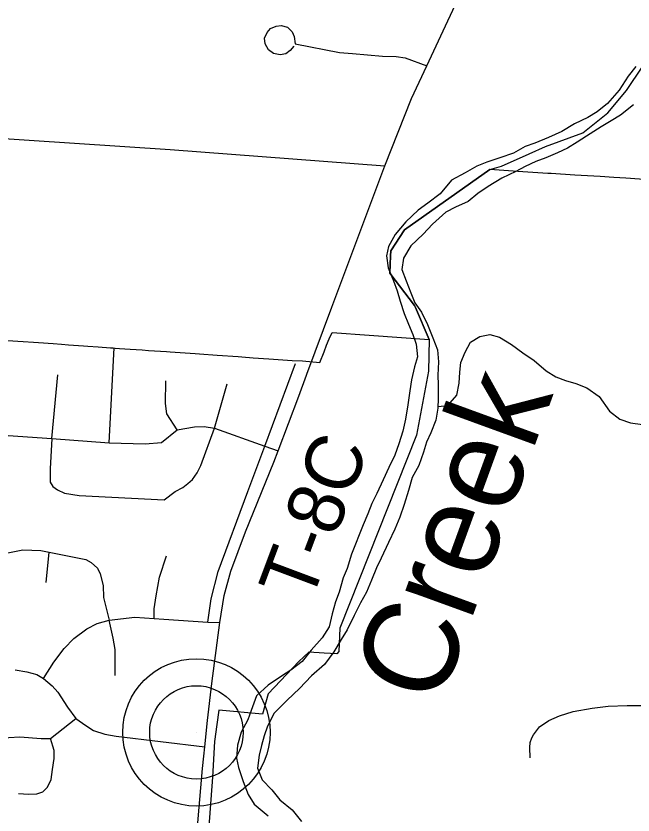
# Model space of a CAD drawing. Extents: x 0 to 34, y 0 to 22.
# Drawn here: x 6.527 to 7.149, y 18.131 to 18.938 of the extents above; entities that cross this region are included whole.
import ezdxf

# ---------------------------------------------------------------- set-up
doc = ezdxf.new("R2010")
doc.units = 0
for name, color, linetype in [('GM_X_City_Street', 7, 'Continuous'), ('GM_X_Corporation', 7, 'Continuous'), ('GM_X_County_Road', 7, 'Continuous'), ('GM_X_Major_River', 7, 'Continuous'), ('GM_X_Major_River_Text', 7, 'Continuous'), ('GM_X_Minor_River', 7, 'Continuous'), ('GM_X_Township_Road', 7, 'Continuous'), ('GM_X_Township_Road_Text', 7, 'Continuous'), ('GM_X_Unincorporated', 7, 'Continuous'), ('GM_X_Unincorporated_Location', 7, 'Continuous')]:
    doc.layers.add(name, color=color, linetype=linetype)

msp = doc.modelspace()

# ---------------------------------------------------------------- linework, layer by layer
at = {"layer": 'GM_X_City_Street'}
for points in [[(6.80693, 18.90727), (6.80336, 18.90299), (6.79908, 18.89966), (6.79338, 18.89871), (6.78649, 18.8999), (6.7815, 18.9037), (6.77817, 18.90964), (6.77746, 18.91558), (6.78008, 18.92129), (6.78364, 18.92509), (6.78934, 18.92746), (6.79433, 18.92818), (6.80075, 18.92651), (6.8055, 18.922), (6.8074, 18.91701), (6.80859, 18.90964), (6.85326, 18.90085), (6.86633, 18.8999), (6.89651, 18.89729), (6.91029, 18.89681), (6.91932, 18.89562), (6.94123, 18.88763)], [(7.04579, 18.18856), (7.04533, 18.19922), (7.04579, 18.20399), (7.04738, 18.20899), (7.04919, 18.21193), (7.05509, 18.21988), (7.06462, 18.22646), (7.07529, 18.231), (7.08913, 18.23554), (7.10815, 18.23891), (7.12441, 18.24084), (7.14343, 18.24139), (7.1619, 18.24139)]]:
    msp.add_lwpolyline(points, dxfattribs=at)
at = {"layer": 'GM_X_Corporation'}
for points in [[(6.51797, 18.61029), (6.53378, 18.60916), (6.54424, 18.60841), (6.54931, 18.60805), (6.56427, 18.60698), (6.57265, 18.60638), (6.57948, 18.6059), (6.59463, 18.60481), (6.59907, 18.6045), (6.60968, 18.60374), (6.62186, 18.60287), (6.62479, 18.60264), (6.62664, 18.60246), (6.63121, 18.60215), (6.64189, 18.60141), (6.65396, 18.60057), (6.66047, 18.60012), (6.67842, 18.59887), (6.68237, 18.59859), (6.70759, 18.59684), (6.71171, 18.59655), (6.72985, 18.59529), (6.75097, 18.59383), (6.75476, 18.59356), (6.76608, 18.59278), (6.78181, 18.59168), (6.80547, 18.59004), (6.81587, 18.58964), (6.83343, 18.58777), (6.8376, 18.59878), (6.8399, 18.60533), (6.84262, 18.61172), (6.84583, 18.61812), (6.88317, 18.61553), (6.94378, 18.61101), (6.92994, 18.6434), (6.92905, 18.64548), (6.90387, 18.67806), (6.90475, 18.69567), (6.905, 18.70079), (6.91892, 18.72181), (7.00507, 18.78268), (7.0166, 18.78615), (7.04449, 18.79861), (7.0612, 18.80608), (7.09889, 18.81996), (7.12418, 18.84003), (7.14302, 18.86275), (7.1594, 18.88705)], [(7.16495, 18.77243), (7.14235, 18.77407), (7.13021, 18.77481), (7.11617, 18.77567), (7.09091, 18.77721), (7.06694, 18.77867), (7.06361, 18.77888), (7.03321, 18.78074), (7.00507, 18.78268), (6.91892, 18.72181), (6.905, 18.70079), (6.90475, 18.69567), (6.90387, 18.67806), (6.92905, 18.64548), (6.92994, 18.6434), (6.94378, 18.61101), (6.9431, 18.57906), (6.93091, 18.51445), (6.85367, 18.31952), (6.85266, 18.29603), (6.85053, 18.29377), (6.8376, 18.29449), (6.82207, 18.29535), (6.81204, 18.28579), (6.78113, 18.25327), (6.77561, 18.23283), (6.73135, 18.23679), (6.72943, 18.22219), (6.72712, 18.20511), (6.72493, 18.16895), (6.7208, 18.11481)]]:
    msp.add_lwpolyline(points, dxfattribs=at)
at = {"layer": 'GM_X_County_Road'}
for points in [[(6.81991, 18.57517), (6.82026, 18.57613), (6.84538, 18.64365), (6.89881, 18.78652), (6.92594, 18.85442), (6.94123, 18.88763), (6.98628, 18.98446), (6.99992, 19.01307), (7.01571, 19.04496), (7.0282, 19.06781), (7.03543, 19.08163), (7.03988, 19.09116), (7.04415, 19.103), (7.04859, 19.11845), (7.05335, 19.14344), (7.08739, 19.34698), (7.09396, 19.37969), (7.09988, 19.41388), (7.10909, 19.47093), (7.10953, 19.47384)], [(6.30332, 18.82829), (6.34149, 18.82565), (6.68224, 18.80302), (6.89881, 18.78652)], [(6.71622, 18.19016), (6.71715, 18.1996), (6.71995, 18.22623), (6.72445, 18.26359), (6.73244, 18.3252), (6.73688, 18.35249), (6.74362, 18.37731), (6.75825, 18.41694), (6.78702, 18.4873), (6.7913, 18.49881), (6.81225, 18.55396), (6.81991, 18.57517)], [(6.68696, 17.79692), (6.69374, 17.89363), (6.69474, 17.90859), (6.69527, 17.91537), (6.69562, 17.92042), (6.69631, 17.93021), (6.69763, 17.94915), (6.69862, 17.96322), (6.69895, 17.96788), (6.70303, 18.026), (6.7034, 18.03105), (6.71041, 18.1271), (6.71501, 18.17789), (6.71622, 18.19016)]]:
    msp.add_lwpolyline(points, dxfattribs=at)
at = {"layer": 'GM_X_Major_River'}
for points in [[(7.15229, 18.88687), (7.14466, 18.87703), (7.13549, 18.86302), (7.12366, 18.84941), (7.11338, 18.84111), (7.10387, 18.83545), (7.09056, 18.82906), (7.07763, 18.82115), (7.06432, 18.81513), (7.05026, 18.80951), (7.04076, 18.80613), (7.02897, 18.79935), (7.01491, 18.79448), (7.00199, 18.79036), (6.99173, 18.78623), (6.97994, 18.77945), (6.96625, 18.77192), (6.9548, 18.75831), (6.94224, 18.74888), (6.93272, 18.74171), (6.92015, 18.73), (6.90946, 18.71714), (6.90258, 18.70502), (6.90063, 18.69554), (6.90247, 18.68338), (6.90772, 18.67045), (6.91146, 18.66018)], [(7.14983, 18.84815), (7.13688, 18.83758), (7.12737, 18.83193), (7.11748, 18.8259), (7.10264, 18.81648), (7.09313, 18.81045), (7.08323, 18.80442), (7.07335, 18.79953), (7.06157, 18.79465), (7.05131, 18.7909), (7.04066, 18.78601), (7.03115, 18.78074), (7.01709, 18.77397), (7.00339, 18.76568), (6.99273, 18.75851), (6.98321, 18.75059)], [(6.98321, 18.75059), (6.97029, 18.74495), (6.9604, 18.73968), (6.94707, 18.72759), (6.93753, 18.71739), (6.92534, 18.70567), (6.91769, 18.69318), (6.91612, 18.6818), (6.92061, 18.67039), (6.92511, 18.65822), (6.92923, 18.64833), (6.93601, 18.63881), (6.94202, 18.62625), (6.94726, 18.61294), (6.95214, 18.60077), (6.95321, 18.58862), (6.95239, 18.57495), (6.95272, 18.56546), (6.95265, 18.55141), (6.95261, 18.54192), (6.95027, 18.52978), (6.94528, 18.5169), (6.94106, 18.50742), (6.93797, 18.49719), (6.93336, 18.48392), (6.92647, 18.4718), (6.92299, 18.45853), (6.91837, 18.44451), (6.91414, 18.43162), (6.90915, 18.41949), (6.90263, 18.40623), (6.89535, 18.39032), (6.89037, 18.38047), (6.88537, 18.36797), (6.88038, 18.35584), (6.87426, 18.34524), (6.86813, 18.33236), (6.86085, 18.31797), (6.85474, 18.30812), (6.84747, 18.29563), (6.83792, 18.28276), (6.82497, 18.27143), (6.81277, 18.25858), (6.80019, 18.24687), (6.78723, 18.23364), (6.78034, 18.22076), (6.77726, 18.21091), (6.77456, 18.20105), (6.77223, 18.19119), (6.77027, 18.17829), (6.77515, 18.1665), (6.78496, 18.1562), (6.79287, 18.14629), (6.80534, 18.13598), (6.81477, 18.12417)], [(6.91146, 18.66018), (6.91445, 18.64992), (6.91856, 18.63737), (6.92268, 18.62672), (6.92718, 18.61607), (6.93055, 18.60656), (6.932, 18.59365), (6.92891, 18.58341), (6.92581, 18.57052), (6.92424, 18.55913), (6.92228, 18.5451), (6.91993, 18.53068), (6.91722, 18.51854), (6.91298, 18.50566), (6.90913, 18.49428), (6.903, 18.48178), (6.89725, 18.46928), (6.89074, 18.45564), (6.88576, 18.44542), (6.88191, 18.43518), (6.87692, 18.42382), (6.8654, 18.39426), (6.86078, 18.37985), (6.85694, 18.37037), (6.85269, 18.35597), (6.84923, 18.34611), (6.84576, 18.33398), (6.84266, 18.32109), (6.83578, 18.30973), (6.82472, 18.29725), (6.81556, 18.2859), (6.80414, 18.27722), (6.79463, 18.27119), (6.7813, 18.26214), (6.76949, 18.25119), (6.76411, 18.2364), (6.76065, 18.22693), (6.75376, 18.21443), (6.75028, 18.20154), (6.74908, 18.18826), (6.75131, 18.17875), (6.75579, 18.16469), (6.76104, 18.15175), (6.76706, 18.14186), (6.78104, 18.13002)]]:
    msp.add_lwpolyline(points, dxfattribs=at)
at = {"layer": 'GM_X_Minor_River'}
msp.add_lwpolyline([(6.95262, 18.54341), (6.96245, 18.5445), (6.97164, 18.55504), (6.97402, 18.56717), (6.9745, 18.57818), (6.97573, 18.58804), (6.97999, 18.59825), (6.98539, 18.60846), (6.99491, 18.61406), (7.00479, 18.61625), (7.01462, 18.6135), (7.02668, 18.60617), (7.03835, 18.59771), (7.04965, 18.59001), (7.06169, 18.57964), (7.07149, 18.57348), (7.0813, 18.56959), (7.09189, 18.56683), (7.10284, 18.56217), (7.11527, 18.5537), (7.12575, 18.5388), (7.13629, 18.53072), (7.14687, 18.52683), (7.15898, 18.52519)], dxfattribs=at)
at = {"layer": 'GM_X_Township_Road'}
for p, q in [((6.62066, 18.50691), (6.62588, 18.60267)), ((6.56265, 18.5113), (6.56884, 18.57541)), ((6.72685, 18.5215), (6.73984, 18.56622)), ((6.55695, 18.36579), (6.56007, 18.39642))]:
    msp.add_line(p, q, dxfattribs=at)
for points in [[(6.72028, 18.32553), (6.72364, 18.34914), (6.73063, 18.37682), (6.76071, 18.45755), (6.77798, 18.50325), (6.80889, 18.58693)], [(6.6892, 18.52002), (6.67887, 18.53609), (6.67751, 18.54637), (6.67785, 18.56956)], [(6.37595, 18.3513), (6.37661, 18.37871), (6.37787, 18.41068), (6.3803, 18.42052), (6.38462, 18.42996), (6.42368, 18.46649), (6.46574, 18.50202), (6.47088, 18.50582), (6.4858, 18.51167), (6.49953, 18.51488), (6.50865, 18.51474), (6.56265, 18.5113), (6.62066, 18.50691), (6.65713, 18.50563), (6.67351, 18.50727), (6.6892, 18.52002), (6.70696, 18.52298), (6.71649, 18.52314), (6.72685, 18.5215), (6.77798, 18.50325), (6.7913, 18.49881)], [(6.56265, 18.5113), (6.56098, 18.48049), (6.56116, 18.46718), (6.56375, 18.46257), (6.56865, 18.45945), (6.57544, 18.45593), (6.59022, 18.45343), (6.67607, 18.44906), (6.68739, 18.45771), (6.69495, 18.46182), (6.70005, 18.46561), (6.70465, 18.46971), (6.70942, 18.47645), (6.7132, 18.48385), (6.72685, 18.5215)], [(6.44891, 18.28813), (6.4527, 18.30519), (6.46154, 18.32319), (6.4726, 18.34466), (6.48776, 18.37088), (6.50179, 18.38521), (6.5068, 18.38969), (6.5114, 18.39266), (6.51829, 18.3956), (6.53354, 18.39878), (6.55173, 18.39807), (6.56007, 18.39642), (6.59726, 18.38907), (6.60253, 18.38594), (6.6089, 18.38014), (6.61148, 18.37439), (6.61472, 18.36267), (6.61504, 18.35066), (6.62056, 18.32777)], [(6.66619, 18.32948), (6.66607, 18.33896), (6.66817, 18.35224), (6.67149, 18.3712), (6.67865, 18.39276)], [(6.55439, 18.26886), (6.56482, 18.28513), (6.57509, 18.29903), (6.58503, 18.30929), (6.59798, 18.31876), (6.60857, 18.32429), (6.62056, 18.32777), (6.64646, 18.33079), (6.66619, 18.32948), (6.67589, 18.32866), (6.72028, 18.32553), (6.73244, 18.3252)], [(6.62657, 18.27171), (6.62657, 18.28766), (6.62688, 18.29792), (6.62483, 18.30945), (6.62056, 18.32777)], [(6.52581, 18.27755), (6.5375, 18.27565), (6.54776, 18.27281), (6.55439, 18.26886), (6.56324, 18.26129), (6.56877, 18.25481), (6.57856, 18.23981), (6.58693, 18.22843), (6.59703, 18.22133), (6.60486, 18.21637), (6.61637, 18.21242), (6.62772, 18.21045), (6.71715, 18.1996)], [(6.45901, 18.06768), (6.46581, 18.09263), (6.4707, 18.11252), (6.47149, 18.11884), (6.47306, 18.14911), (6.47654, 18.17285), (6.47844, 18.17933), (6.4846, 18.18769), (6.49281, 18.1967), (6.50118, 18.20254), (6.50908, 18.2068), (6.51934, 18.20933), (6.53039, 18.20996), (6.55219, 18.20822), (6.5615, 18.20822), (6.58693, 18.22843)], [(6.52929, 18.15264), (6.53924, 18.15201), (6.54761, 18.15216), (6.55361, 18.15437), (6.5585, 18.15895), (6.56214, 18.16669), (6.56356, 18.1768), (6.56498, 18.18785), (6.56498, 18.19606), (6.5615, 18.20822)]]:
    msp.add_lwpolyline(points, dxfattribs=at)
at = {"layer": 'GM_X_Unincorporated'}
for radius in [0.0744, 0.04716]:
    msp.add_circle((6.70875, 18.21431), radius, dxfattribs=at)
at = {"layer": 'GM_X_Unincorporated_Location'}
msp.add_line((6.70875, 18.21431), (6.70875, 18.21431), dxfattribs=at)

# ---------------------------------------------------------------- texts
at = {"layer": 'GM_X_Major_River_Text'}
msp.add_text('Creek', height=0.094695, rotation=70.0013, dxfattribs=at).set_placement((6.95379, 18.2388))
at = {"layer": 'GM_X_Township_Road_Text'}
msp.add_text('T-8C', height=0.056818, rotation=69.41395, dxfattribs=at).set_placement((6.82378, 18.34338))

doc.saveas('drawing.dxf')
